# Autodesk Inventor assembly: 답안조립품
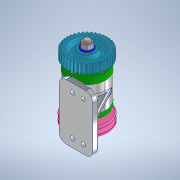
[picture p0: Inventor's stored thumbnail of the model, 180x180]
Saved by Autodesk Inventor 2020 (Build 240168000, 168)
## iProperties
Created: 2023-08
Part Number: 답안조립품
Document SubType Name: Assembly
Designer: oem
Author: oem
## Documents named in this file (12)
- C:\Users\oem\Desktop\730806V1005\답안조립품.iam
- C:\Users\oem\Desktop\730806V1005\본체.ipt
- C:\Users\oem\Desktop\730806V1005\베어링 6204.ipt
- C:\Users\oem\Desktop\730806V1005\축.ipt
- C:\Users\oem\Desktop\730806V1005\커버.ipt
- C:\Users\oem\Desktop\730806V1005\오일실 20x35x8.ipt
- C:\Users\oem\Desktop\730806V1005\볼트 M4 x 12.ipt
- C:\Users\oem\Desktop\730806V1005\키 5x5.ipt
- C:\Users\oem\Desktop\730806V1005\V벨트풀리.ipt
- C:\Users\oem\Desktop\730806V1005\스퍼기어.ipt
- C:\Users\oem\Desktop\730806V1005\와셔 12x24.ipt
- C:\Users\oem\Desktop\730806V1005\너트 M12x1.25.ipt
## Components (1 placed, 1 different names)
1. V벨트풀리:1
